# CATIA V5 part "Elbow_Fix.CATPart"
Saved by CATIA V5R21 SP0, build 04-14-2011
Part number: Elbow_Fix
Bounding box of the stored display mesh (mm): x -31.165 to 10.835, y -26.172 to -21.172, z 266.996 to 326.996
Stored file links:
  F:\教程\Robotic_Arm_Arduino_Kinect\机械臂CAD\Arm_Detailed_Design\Elbow_Fix.CATPart
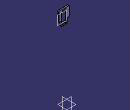
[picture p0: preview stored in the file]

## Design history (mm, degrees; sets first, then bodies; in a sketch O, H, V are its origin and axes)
Body1 (main body)
  DatumSurface1
  Plane1: type Offset, RefPlane DatumSurface1, Offset 20, reversed
  Plane2: stored without definition
  Sketch1 on Plane1, origin (0, -21.172, 0), H (1, 0, 0), V (0, 0, 1)
    construction line L1 (-10.1648, 341.8213) -> (-10.1648, 244.011)
    line L2 (-20.6648, 317.246) -> (0.3352, 317.246)
    line L3 (0.3352, 317.246) -> (0.3352, 276.746)
    line L4 (0.3352, 276.746) -> (-20.6648, 276.746)
    line L5 (-20.6648, 276.746) -> (-20.6648, 317.246)
    construction line L6 (-52.7787, 296.996) -> (51.9307, 296.996)
    circle A1 centre (-15.1648, 321.246) radius 2.5
    point P9 (-15.1648, 321.246)
    circle A2 centre (-5.1648, 321.246) radius 2.5
    circle A3 centre (-5.1648, 272.746) radius 2.5
    circle A4 centre (-15.1648, 272.746) radius 2.5
    line L7 (-28.1648, 326.996) -> (7.8352, 326.996)
    line L8 (10.8352, 323.996) -> (10.8352, 286.996)
    point P13 (10.8352, 286.996)
    point P14 (-2.1648, 265.0366)
    point P15 (-31.1648, 286.996)
    line L9 (-31.1648, 286.996) -> (-31.1648, 323.996)
    point P16 (-31.1648, 326.996)
    reference intersected line E1 through (-10.1648, 0) direction (0, 1) from Plane2
    line L10 (-31.1648, 286.996) -> (-26.1648, 286.996)
    point P17 (-23.1648, 286.996)
    line L11 (-23.1648, 283.996) -> (-23.1648, 269.996)
    line L12 (-20.1648, 266.996) -> (-0.1648, 266.996)
    line L13 (2.8352, 269.996) -> (2.8352, 283.996)
    point P18 (2.8352, 286.996)
    line L14 (5.8352, 286.996) -> (10.8352, 286.996)
    arc A5 centre (-0.1648, 269.996) radius 3 from (2.8352, 269.996) to (-0.1648, 266.996) cw
    arc A6 centre (-20.1648, 269.996) radius 3 from (-20.1648, 266.996) to (-23.1648, 269.996) cw
    arc A7 centre (-26.1648, 283.996) radius 3 from (-26.1648, 286.996) to (-23.1648, 283.996) cw
    arc A8 centre (5.8352, 283.996) radius 3 from (2.8352, 283.996) to (5.8352, 286.996) cw
    arc A9 centre (7.8352, 323.996) radius 3 from (7.8352, 326.996) to (10.8352, 323.996) cw
    arc A10 centre (-28.1648, 323.996) radius 3 from (-28.1648, 326.996) to (-31.1648, 323.996) ccw
    length L3 = 40.5
    length L4 = 21
    distance L3 L1 = 10.5
    distance L2 L6 = 20.25
    radius A1 = 2.5
    distance P9 L2 = 4
    distance L1 P9 = 5
    distance L8 L9 = 42
    distance P14 L1 = 8
    distance P13 L1 = 21
    distance L7 L6 = 30
    distance L7 L12 = 60
    radius A5 = 3
    radius A6 = 3
    distance P15 P17 = 8
    radius A7 = 3
    distance P18 P13 = 8
    radius A8 = 3
    radius A9 = 3
    distance P15 P16 = 40
    radius A10 = 3
    vertical: L1 V, L3 V, L5 V, L8 V, L9 V, L11 V, L13 V
    horizontal: L2 H, L4 H, L6 H, L7 H, L10 H, L12 H, L14 H
    symmetry: A1 A2 L1, A2 A3 L6, A1 A4 L6
    coincidence: E1 L1, P18 L10, L10 P17, L11 P17, L13 P18, L14 P18, L7 P16, L9 P16
    tangency: A5 L13, A5 L12, A6 L12, A6 L11, A7 L10, A7 L11, A8 L13, A8 L14, A9 L7, A9 L8, A10 L7, A10 L9
  Pad1: profile Sketch1, direction (0, -1, 0), length 5
  Sketch2 on face of Pad1 from Sketch1.L8, origin (10.8352, 0, 0), H (0, 1, 0), V (0, 0, 1)
    circle A1 centre (-23.672, 314.586) radius 1.25
    point P1 (-23.672, 314.586)
    reference projected line E1 (-21.172, 286.996) -> (-21.172, 323.996) from edge [start face of Pad1 | face of Pad1 from Sketch1.L8]
    reference intersected line E2 through (0, 326.996) direction (1, 0) from face of Pad1 from Sketch1.L7
    circle A2 centre (-23.672, 297.586) radius 1.25
    point P2 (-23.672, 297.586)
    reference projected line E3 (-21.172, 286.996) -> (-21.172, 323.996) from edge [start face of Pad1 | face of Pad1 from Sketch1.L8]
    radius A1 = 1.25
    distance P1 E1 = 2.5
    distance P1 E2 = 12.41
    radius A2 = 1.25
    distance P2 P1 = 17
    distance P2 E3 = 2.5
  Pocket1: profile Sketch2, direction (-1, 0, 0), length 5
  Sketch3 on face of Pad1 from Sketch1.L9, origin (-31.1648, 0, 0), H (0, -1, 0), V (0, 0, 1)
    circle A1 centre (23.672, 314.586) radius 1.25
    point P1 (23.672, 314.586)
    circle A2 centre (23.672, 297.586) radius 1.25
    point P2 (23.672, 297.586)
    reference intersected line E1 through (0, 326.996) direction (1, 0) from face of Pad1 from Sketch1.L7
    reference projected line E2 (26.172, 323.996) -> (26.172, 286.996) from edge [face of Pad1 from Sketch1.L9 | end face of Pad1]
    reference projected line E3 (26.172, 323.996) -> (26.172, 286.996) from edge [face of Pad1 from Sketch1.L9 | end face of Pad1]
    radius A2 = 1.25
    radius A1 = 1.25
    distance P1 P2 = 17
    distance P1 E1 = 12.41
    distance P1 E2 = 2.5
    distance P2 E3 = 2.5
  Pocket2: profile Sketch3, direction (1, 0, 0), length 5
